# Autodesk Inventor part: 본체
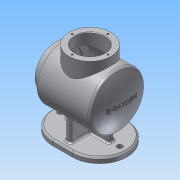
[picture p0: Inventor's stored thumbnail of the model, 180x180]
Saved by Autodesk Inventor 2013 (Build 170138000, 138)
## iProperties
Created: 2016-04
Part Number: 본체
Material: 알루미늄 6061
Document SubType Name: Modeling
Designer: Administrator
Density: 2.71 g/cm^3
Mass: 893.7 g
Surface Area: 1236.2 cm^2
Volume: 329.779 cm^3
Author: Administrator
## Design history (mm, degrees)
sketch "스케치1"
  geometry: 1 further point
sketch "스케치2"
  geometry: L1 (-17.5, 50)-(17.5, 50); L2 (-17.5, -50)-(17.5, -50); A1 r 50 centre (17.5, 0) between (17.5, -50) and (17.5, 50); A2 r 50 centre (-17.5, 0) between (-17.5, 50) and (-17.5, -50); 1 further point
  constraints: 4 end point, 4 point on circle, 2 centre point, 2 tangent, 1 horizontal, 1 parallel
  dimensions: "d7" = 0 vertical distance of A1.centre point (0, 0); "d8" = 100 diameter of A1; "d9" = 100 diameter of A2; "d10" = 0 vertical distance of point (0, 0) A2.centre; "d12" = 17.5 distance of A1.centre point (0, 0); "d13" = 17.5 distance of point (0, 0) A2.centre
extrude "돌출1" new body sketch "스케치2" distance "d14" = 10; taper "d15" = 0 deg
node "작업 평면1"
sketch "스케치3"
  geometry: L1 (-71.207, 79)-(106.129, 79); L2 (-44.5, 79)-(-44.5, 117); L3 (-44.5, 117)-(-32.5, 117); L4 (-32.5, 117)-(-32.5, 129); L5 (-32.5, 129)-(66.587, 129); L6 (-50, 0)-(0, 0) reference; L7 (85, 0)-(85, 10) reference; L8 (-50, 0)-(-50, 10) reference; L9 (64.645, 126)-(-29.5, 126); L10 (-29.5, 126)-(-29.5, 114); L11 (-29.5, 114)-(-41.5, 114); L12 (-41.5, 114)-(-41.5, 79); L13 (77.5, 79)-(74.5, 79); L14 (-41.5, 79)-(-44.5, 79); A1 r 120 centre (-42.5, 79) between (77.5, 79) and (66.587, 129); A2 r 117 centre (-42.5, 79) between (74.5, 79) and (64.645, 126); 1 further point
  constraints: 22 end point, 4 parallel, 4 point on circle, 3 perpendicular, 3 point on line, 2 centre point, 2 collinear, 1 horizontal, 4 other
  dimensions: "d16" = 79 distance from line of point (17.5, 0) L1; "d17" = 76 diameter of L3 L1; "d18" = 100 diameter of L5 L1; "d19" = 12 distance of L2.end L3.end; "d23" = 240 diameter of A1; "d25" = 2 distance from line of A1.centre L2; "d26" = 5.5 distance between parallel lines of L8 L2; "d27" = 3 radial gap between concentric circles of A1 A2
revolve "회전1" sketch "스케치3" stored, may be unused: angle "d28" = 90 deg
sketch "스케치4"
  geometry: C1 r 38 at (0, 0) reference; C2 r 35 at (0, 0); 1 further point
  constraints: 1 centre point, 1 coincident
  dimensions: "d29" = 70 diameter of C2
extrude "돌출2" cut sketch "스케치4" distance "d32" = 12; taper "d33" = 0 deg
sketch "스케치5"
  geometry: C1 r 35 at (0, 0) reference; C2 r 38 at (0, 0) reference; C3 r 27 at (0, 0); 1 further point
  constraints: 1 centre point, 1 coincident
  dimensions: "d34" = 54 diameter of C3
extrude "돌출3" join sketch "스케치5" distance "d36" = 12; taper "d37" = 0 deg
sketch "스케치6"
  geometry: L1 (50, 10)-(50, 0) reference; L2 (50, 0)-(-50, 0) reference; L3 (-50, 0)-(-50, 10) reference; L4 (-50, 10)-(50, 10) reference; L5 (40, 10)-(40, 14.339); L6 (40, 14.339)-(40, 49); L7 (-40, 10)-(-40, 49); C1 r 47 at (0, 79) reference; A1 r 50 centre (0, 79) between (40, 49) and (-40, 49) reference; 1 further point
  constraints: 6 end point, 3 perpendicular, 2 point on circle, 2 point on line
  dimensions: "d40" = 40 distance from line of A1.centre L7; "d41" = 40 distance from line of L6 point (0, 0)
extrude "돌출4" join sketch "스케치6" stored distance "d42" = 10; taper "d43" = 0 deg
node "작업 평면2"
sketch "스케치7"
  geometry: L1 (-50, 0)-(-50, 10) reference; L2 (-50, 10)-(12.5, 10) reference; L3 (12.5, 10)-(12.5, 29) reference; L4 (12.5, 29)-(-32.5, 29) reference; L5 (-32.5, 29)-(-32.5, 41) reference; L6 (-32.5, 41)-(-44.5, 41) reference; L7 (-44.5, 41)-(-44.5, 52) reference; L8 (-44.5, 52)-(-32.5, 52) reference; L9 (-32.5, 52)-(-32.5, 44) reference; L10 (-32.5, 44)-(-29.5, 44) reference; L11 (-29.5, 44)-(-29.5, 32) reference; L12 (-29.5, 32)-(64.645, 32) reference; L13 (64.645, 126)-(-29.5, 126) reference; L14 (-29.5, 126)-(-29.5, 114) reference; L15 (-29.5, 114)-(-32.5, 114) reference; L16 (-32.5, 114)-(-32.5, 106) reference; L17 (-32.5, 106)-(-44.5, 106) reference; L18 (-44.5, 106)-(-44.5, 117) reference; L19 (-44.5, 117)-(-32.5, 117) reference; L20 (-32.5, 117)-(-32.5, 129) reference; L21 (-32.5, 129)-(66.587, 129) reference; L22 (66.587, 29)-(22.5, 29) reference; L23 (22.5, 29)-(22.5, 10) reference; L24 (22.5, 10)-(85, 10) reference; L25 (85, 10)-(85, 0) reference; L26 (85, 0)-(-50, 0) reference; L27 (54.15, 29)-(57.5, 10); A1 r 117 centre (-42.5, 79) between (64.645, 32) and (64.645, 126) reference; A2 r 120 centre (-42.5, 79) between (66.587, 29) and (66.587, 129) reference; 1 further point
  constraints: 2 end point, 2 point on line
  dimensions: "d44" = 40 horizontal distance of L27.end point (17.5, 0); "d46" = 100 deg angle of L24 L27
feature "리브1" sketch "스케치7" dims "d48" = 1, "d49" = 10, "d50" = 0, "d51" = 0, "d52" = 1, "d53" = 1
fillet "모깎기1" dims "d54" = 3
fillet "모깎기2" dims "d55" = 3
chamfer "모따기1" distance "d56" = 3; stored, may be unused: second distance "d57" = 2, angle "d58" = 45 deg
fillet "모깎기3" dims "d59" = 5
fillet "모깎기4" dims "d60" = 0.2
node "작업 평면3"
sketch "스케치8"
  geometry: L1 (-50, -45)-(-50, 45) reference; L2 (-17.5, -50)-(17.5, -50) reference; C1 r 38 at (0, 0); 1 further point
  constraints: 1 centre point
  dimensions: "d62" = 50 distance from line of L1 C1.centre; "d64" = 50 distance from line of L2 C1.centre; "d65" = 76 diameter of C1
extrude "돌출5" join sketch "스케치8" stored distance "d66" = 10; taper "d67" = 0 deg
sketch "스케치9"
  geometry: C1 r 38 at (0, 0) reference; C2 r 27 at (0, 0); 1 further point
  constraints: 1 centre point, 1 coincident
  dimensions: "d68" = 54 diameter of C2
extrude "돌출6" cut sketch "스케치9" distance "d70" = 56.5; taper "d71" = 0 deg
chamfer "모따기2" distance "d72" = 1; stored, may be unused: second distance "d73" = 2, angle "d74" = 45 deg
chamfer "모따기3" distance "d75" = 1; stored, may be unused: second distance "d76" = 2, angle "d77" = 45 deg
sketch "스케치10"
  geometry: L1 (0, 0)-(32.5, 0); C1 r 28 at (0, 0) reference; 2 further points
  constraints: 2 end point, 1 coincident, 1 horizontal
  dimensions: "d78" = 32.5 distance of L1.start L1.end
hole "구멍1" sketch "스케치10" at (32.5, 0) diameter "d79" = 3.242; stored, may be unused: countersink angle "d83" = 90 deg, drill point angle "d85" = 118 deg; dims "d80" = 8, "d81" = 4, "d82" = 2, "d84" = 10
sketch "스케치11"
  geometry: L1 (0, 0)-(0, 32.5); C1 r 28 at (0, 0) reference; 2 further points
  constraints: 2 end point, 1 coincident, 1 vertical
  dimensions: "d89" = 32.5 distance of L1.start L1.end
hole "구멍2" sketch "스케치11" at (0, 32.5) diameter "d90" = 3.242; stored, may be unused: countersink angle "d94" = 90 deg, drill point angle "d96" = 118 deg; dims "d91" = 8, "d92" = 4, "d93" = 2, "d95" = 10
node "작업 평면4"
sketch "스케치12"
  geometry: L1 (-24.784, 15.761)-(24.784, 15.761); L2 (24.784, 15.761)-(24.784, -15.761); L3 (24.784, -15.761)-(-24.784, -15.761); L4 (-24.784, -15.761)-(-24.784, 15.761); L5 (-24.784, 0)-(24.784, 0); L6 (0, 15.761)-(0, -15.761); 2 further points
  constraints: 4 end point, 4 midpoint, 2 other
  dimensions: "d101" = 0 distance from line of point (0, 0) L6; "d102" = 0 distance from line of L5 point (0, 0)
feature "엠보싱1" sketch "스케치12" dims "d7" = 0, "d103" = 0.5, "d104" = 0
sketch "스케치13"
  geometry: C1 r 5 at (54, 0); C2 r 5 at (-54, 0); 1 further point
  constraints: 2 centre point
  dimensions: "d105" = 0 vertical distance of C2.centre point (0, 0); "d106" = 0 vertical distance of C1.centre point (0, 0); "d107" = 10 diameter of C1; "d108" = 10 diameter of C2; "d109" = 54 distance of C1.centre point (0, 0); "d110" = 54 distance of C2.centre point (0, 0)
extrude "돌출7" cut sketch "스케치13" distance "d111" = 56.5; taper "d112" = 0 deg
fillet "모깎기5" dims "d113" = 3
sketch "스케치14"
  geometry: 1 further point
node "솔리드1"
mirror "대칭1"
pattern_circular "원형 패턴1" dims angle "d87" = 360 deg
pattern_circular "원형 패턴2" dims angle "d98" = 360 deg
node "절단 모서리 투영1"
node "절단 모서리 투영2"
other parameters: "d61" = -144, "d100" = -155
